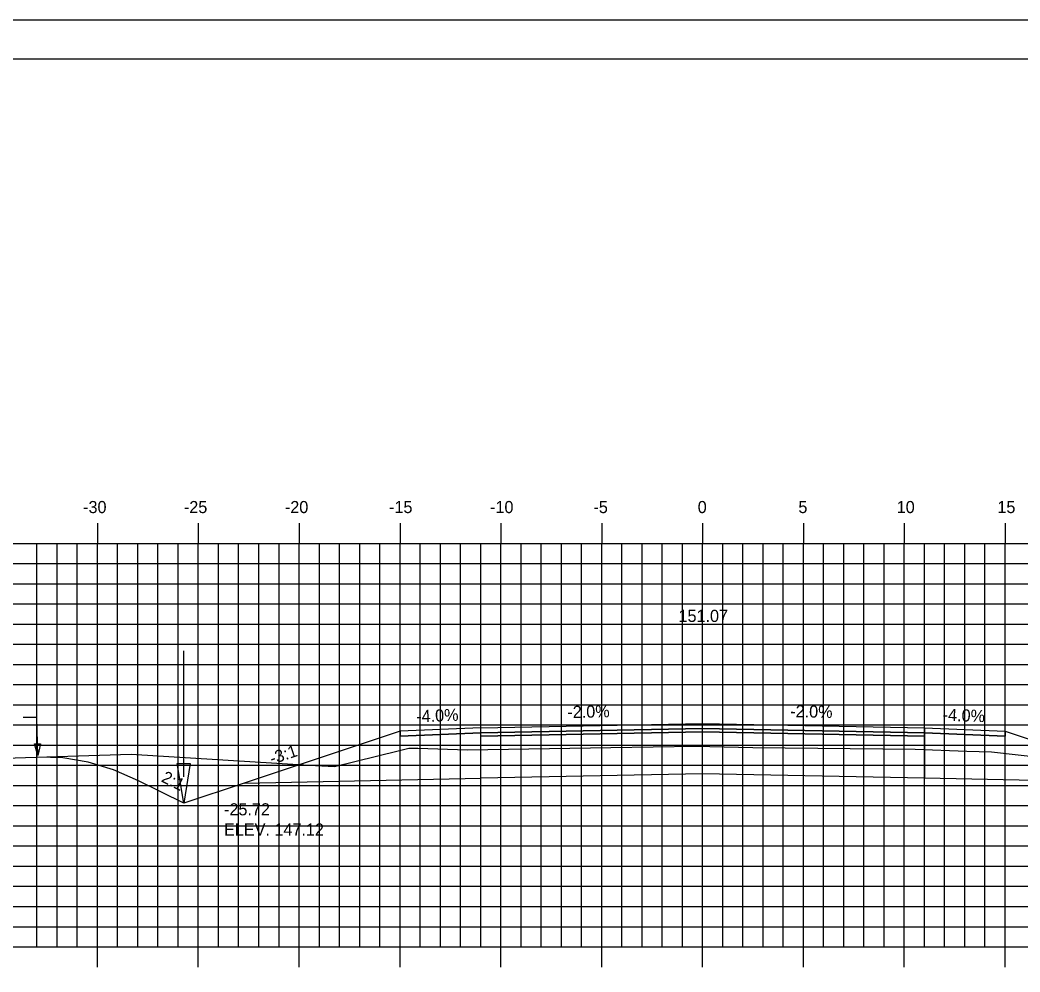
# Model space of a CAD drawing. Extents: x 1147190 to 1147360, y 608981 to 609091.
# Drawn here: x 1147239.1 to 1147288.68, y 609044.09 to 609091.28 of the extents above; entities that cross this region are included whole.
import ezdxf

# ---------------------------------------------------------------- set-up
doc = ezdxf.new("R2010")
doc.units = 0
for name, color, linetype in [('ANNOTATION', 7, 'Continuous'), ('BORDER', 7, 'Continuous'), ('D_Drainage_Ditch_Line', 7, 'Continuous'), ('D_Roadway_Centerline', 7, 'Continuous'), ('D_Roadway_Centerline_Text', 7, 'Continuous'), ('D_Roadway_Edge_Shoulder', 7, 'Continuous'), ('D_Roadway_Edge_TW', 7, 'Continuous'), ('D_Roadway_Pavement', 7, 'Continuous'), ('D_Roadway_SlopeLines', 7, 'Continuous'), ('D_Roadway_SubGrade', 7, 'Continuous'), ('D_Text_Standard', 7, 'Continuous'), ('H_V ANNOTATION', 7, 'Continuous'), ('MAJOR', 7, 'Continuous'), ('MINOR', 7, 'Continuous'), ('PLOT BOUNDARY', 7, 'Continuous'), ('S_Roadway_Centerline', 7, 'Continuous')]:
    doc.layers.add(name, color=color, linetype=linetype)

msp = doc.modelspace()

# ---------------------------------------------------------------- linework, layer by layer
at = {"layer": 'BORDER'}
msp.add_lwpolyline([(1147197.941, 608984.335), (1147357.941, 608984.335), (1147357.941, 609089.335), (1147197.941, 609089.335)], close=True, dxfattribs=at)
at = {"layer": 'D_Drainage_Ditch_Line'}
msp.add_line((1147247.216, 609053.765), (1147247.217, 609060.009), dxfattribs=at)
msp.add_lwpolyline([(1147246.888, 609054.422), (1147247.544, 609054.422), (1147247.216, 609052.453)], close=True, dxfattribs=at)
at = {"layer": 'D_Roadway_Edge_Shoulder'}
for points in [[(1147261.941, 609056.188), (1147257.941, 609056.028), (1147257.941, 609055.778), (1147261.941, 609055.938)], [(1147283.941, 609056.188), (1147287.941, 609056.028), (1147287.941, 609055.778), (1147283.941, 609055.938)]]:
    msp.add_lwpolyline(points, close=True, dxfattribs=at)
at = {"layer": 'D_Roadway_Edge_TW'}
msp.add_lwpolyline([(1147261.941, 609055.938), (1147261.941, 609056.188), (1147272.941, 609056.408), (1147283.941, 609056.188), (1147283.941, 609055.938), (1147272.941, 609056.158)], close=True, dxfattribs=at)
at = {"layer": 'D_Roadway_Pavement'}
msp.add_lwpolyline([(1147261.941, 609055.771), (1147261.941, 609055.938), (1147272.941, 609056.158), (1147283.941, 609055.938), (1147283.941, 609055.771), (1147272.941, 609055.991)], close=True, dxfattribs=at)
at = {"layer": 'D_Roadway_SlopeLines'}
for points in [[(1147247.216, 609052.453), (1147244.981, 609053.571), (1147243.731, 609054.113), (1147242.481, 609054.488), (1147241.231, 609054.698), (1147239.981, 609054.741)], [(1147250.216, 609053.453), (1147247.216, 609052.453)]]:
    msp.add_lwpolyline(points, dxfattribs=at)
at = {"layer": 'D_Roadway_SubGrade'}
for points in [[(1147261.941, 609055.771), (1147261.941, 609055.938), (1147257.941, 609055.778), (1147257.941, 609056.028), (1147257.94, 609056.028), (1147250.216, 609053.453), (1147261.941, 609053.688)], [(1147261.941, 609053.688), (1147261.941, 609055.771), (1147272.941, 609055.991), (1147283.941, 609055.771), (1147283.941, 609053.688), (1147272.941, 609053.908)], [(1147283.941, 609055.771), (1147283.941, 609055.938), (1147287.941, 609055.778), (1147287.941, 609056.028), (1147287.941, 609056.028), (1147295.664, 609053.453), (1147283.941, 609053.688)]]:
    msp.add_lwpolyline(points, close=True, dxfattribs=at)
at = {"layer": 'D_Text_Standard'}
msp.add_lwpolyline([(1147239.981, 609054.821), (1147239.939, 609056.696), (1147239.259, 609056.696)], dxfattribs=at)
msp.add_lwpolyline([(1147239.981, 609054.821), (1147239.823, 609055.399), (1147240.114, 609055.406)], close=True, dxfattribs=at)
at = {"layer": 'MAJOR'}
for p, q in [((1147242.941, 609066.337), (1147242.941, 609065.335)), ((1147247.941, 609066.337), (1147247.941, 609065.335)), ((1147252.941, 609066.337), (1147252.941, 609065.335)), ((1147257.941, 609066.337), (1147257.941, 609065.335)), ((1147262.941, 609066.337), (1147262.941, 609065.335)), ((1147267.941, 609066.337), (1147267.941, 609065.335)), ((1147272.941, 609066.337), (1147272.941, 609065.335)), ((1147277.941, 609066.337), (1147277.941, 609065.335)), ((1147282.941, 609066.337), (1147282.941, 609065.335)), ((1147287.941, 609066.337), (1147287.941, 609065.335)), ((1147202.941, 609065.335), (1147342.941, 609065.335)), ((1147202.941, 609065.335), (1147342.941, 609065.335)), ((1147242.941, 609045.335), (1147242.941, 609065.335)), ((1147247.941, 609045.335), (1147247.941, 609065.335)), ((1147252.941, 609045.335), (1147252.941, 609065.335)), ((1147257.941, 609045.335), (1147257.941, 609065.335)), ((1147262.941, 609045.335), (1147262.941, 609065.335)), ((1147267.941, 609045.335), (1147267.941, 609065.335)), ((1147272.941, 609045.335), (1147272.941, 609065.335)), ((1147277.941, 609045.335), (1147277.941, 609065.335)), ((1147282.941, 609045.335), (1147282.941, 609065.335)), ((1147287.941, 609045.335), (1147287.941, 609065.335)), ((1147202.941, 609060.335), (1147342.941, 609060.335)), ((1147202.941, 609055.335), (1147342.941, 609055.335)), ((1147202.941, 609050.335), (1147342.941, 609050.335)), ((1147202.941, 609045.335), (1147342.941, 609045.335)), ((1147202.941, 609045.335), (1147342.941, 609045.335)), ((1147242.941, 609044.333), (1147242.941, 609045.335)), ((1147247.941, 609044.333), (1147247.941, 609045.335)), ((1147252.941, 609044.333), (1147252.941, 609045.335)), ((1147257.941, 609044.333), (1147257.941, 609045.335)), ((1147262.941, 609044.333), (1147262.941, 609045.335)), ((1147267.941, 609044.333), (1147267.941, 609045.335)), ((1147272.941, 609044.333), (1147272.941, 609045.335)), ((1147277.941, 609044.333), (1147277.941, 609045.335)), ((1147282.941, 609044.333), (1147282.941, 609045.335)), ((1147287.941, 609044.333), (1147287.941, 609045.335))]:
    msp.add_line(p, q, dxfattribs=at)
at = {"layer": 'MINOR'}
for p, q in [((1147239.941, 609045.335), (1147239.941, 609065.335)), ((1147240.941, 609045.335), (1147240.941, 609065.335)), ((1147241.941, 609045.335), (1147241.941, 609065.335)), ((1147243.941, 609045.335), (1147243.941, 609065.335)), ((1147244.941, 609045.335), (1147244.941, 609065.335)), ((1147245.941, 609045.335), (1147245.941, 609065.335)), ((1147246.941, 609045.335), (1147246.941, 609065.335)), ((1147248.941, 609045.335), (1147248.941, 609065.335)), ((1147249.941, 609045.335), (1147249.941, 609065.335)), ((1147250.941, 609045.335), (1147250.941, 609065.335)), ((1147251.941, 609045.335), (1147251.941, 609065.335)), ((1147253.941, 609045.335), (1147253.941, 609065.335)), ((1147254.941, 609045.335), (1147254.941, 609065.335)), ((1147255.941, 609045.335), (1147255.941, 609065.335)), ((1147256.941, 609045.335), (1147256.941, 609065.335)), ((1147258.941, 609045.335), (1147258.941, 609065.335)), ((1147259.941, 609045.335), (1147259.941, 609065.335)), ((1147260.941, 609045.335), (1147260.941, 609065.335)), ((1147261.941, 609045.335), (1147261.941, 609065.335)), ((1147263.941, 609045.335), (1147263.941, 609065.335)), ((1147264.941, 609045.335), (1147264.941, 609065.335)), ((1147265.941, 609045.335), (1147265.941, 609065.335)), ((1147266.941, 609045.335), (1147266.941, 609065.335)), ((1147268.941, 609045.335), (1147268.941, 609065.335)), ((1147269.941, 609045.335), (1147269.941, 609065.335)), ((1147270.941, 609045.335), (1147270.941, 609065.335)), ((1147271.941, 609045.335), (1147271.941, 609065.335)), ((1147273.941, 609045.335), (1147273.941, 609065.335)), ((1147274.941, 609045.335), (1147274.941, 609065.335)), ((1147275.941, 609045.335), (1147275.941, 609065.335)), ((1147276.941, 609045.335), (1147276.941, 609065.335)), ((1147278.941, 609045.335), (1147278.941, 609065.335)), ((1147279.941, 609045.335), (1147279.941, 609065.335)), ((1147280.941, 609045.335), (1147280.941, 609065.335)), ((1147281.941, 609045.335), (1147281.941, 609065.335)), ((1147283.941, 609045.335), (1147283.941, 609065.335)), ((1147284.941, 609045.335), (1147284.941, 609065.335)), ((1147285.941, 609045.335), (1147285.941, 609065.335)), ((1147286.941, 609045.335), (1147286.941, 609065.335)), ((1147202.941, 609064.335), (1147342.941, 609064.335)), ((1147202.941, 609063.335), (1147342.941, 609063.335)), ((1147202.941, 609062.335), (1147342.941, 609062.335)), ((1147202.941, 609061.335), (1147342.941, 609061.335)), ((1147202.941, 609059.335), (1147342.941, 609059.335)), ((1147202.941, 609058.335), (1147342.941, 609058.335)), ((1147202.941, 609057.335), (1147342.941, 609057.335)), ((1147202.941, 609056.335), (1147342.941, 609056.335)), ((1147202.941, 609054.335), (1147342.941, 609054.335)), ((1147202.941, 609053.335), (1147342.941, 609053.335)), ((1147202.941, 609052.335), (1147342.941, 609052.335)), ((1147202.941, 609051.335), (1147342.941, 609051.335)), ((1147202.941, 609049.335), (1147342.941, 609049.335)), ((1147202.941, 609048.335), (1147342.941, 609048.335)), ((1147202.941, 609047.335), (1147342.941, 609047.335)), ((1147202.941, 609046.335), (1147342.941, 609046.335))]:
    msp.add_line(p, q, dxfattribs=at)
at = {"layer": 'PLOT BOUNDARY'}
msp.add_lwpolyline([(1147189.848, 608981.276), (1147359.848, 608981.276), (1147359.848, 609091.276), (1147189.848, 609091.276)], close=True, dxfattribs=at)
at = {"layer": 'S_Roadway_Centerline'}
msp.add_lwpolyline([(1147218.688, 609053.977), (1147226.482, 609054.305), (1147226.795, 609054.318), (1147244.605, 609054.889), (1147253.434, 609054.334), (1147254.688, 609054.274), (1147257.845, 609055.05), (1147258.383, 609055.178), (1147258.823, 609055.179), (1147261.29, 609055.101), (1147268.386, 609055.21), (1147272.587, 609055.279), (1147275.438, 609055.212), (1147283.483, 609055.129), (1147286.037, 609055.041), (1147287.273, 609054.996), (1147292.854, 609054.376), (1147294.865, 609054.203), (1147300.019, 609054.043), (1147301.689, 609053.963), (1147303.16, 609054.01), (1147308.976, 609054.019), (1147310.153, 609054.07), (1147311.998, 609054.066)], dxfattribs=at)

# ---------------------------------------------------------------- texts
at = {"layer": 'ANNOTATION'}
for s, rotation, p in [('-4.0%', 2.2906, (1147258.757, 609056.461)), ('-2.0%', 1.1458, (1147266.244, 609056.674)), ('-2.0%', 358.8542, (1147277.284, 609056.721)), ('-4.0%', 357.7094, (1147284.837, 609056.553)), ('-3:1', 18.4348, (1147251.595, 609054.367)), ('2:1', 333.4349, (1147246.066, 609053.546))]:
    msp.add_text(s, height=0.6, rotation=rotation, dxfattribs=at).set_placement(p)
at = {"layer": 'D_Roadway_Centerline'}
for s, p in [('C', (1147272.936, 609056.408)), ('L', (1147272.941, 609056.4))]:
    msp.add_text(s, height=0.0146, dxfattribs=at).set_placement(p)
at = {"layer": 'D_Roadway_Centerline_Text'}
msp.add_text('151.07', height=0.6, dxfattribs=at).set_placement((1147271.748, 609061.44))
at = {"layer": 'D_Text_Standard'}
for s, p in [('-25.72', (1147249.216, 609051.853)), ('ELEV. 147.12', (1147249.216, 609050.851))]:
    msp.add_text(s, height=0.6, dxfattribs=at).set_placement(p)
at = {"layer": 'H_V ANNOTATION'}
for s, p in [('-30', (1147242.229, 609066.835)), ('-25', (1147247.226, 609066.835)), ('-20', (1147252.234, 609066.835)), ('-15', (1147257.398, 609066.835)), ('-10', (1147262.406, 609066.835)), ('-5', (1147267.531, 609066.835)), ('0', (1147272.7, 609066.835)), ('5', (1147277.692, 609066.835)), ('10', (1147282.566, 609066.835)), ('15', (1147287.558, 609066.835))]:
    msp.add_text(s, height=0.6, dxfattribs=at).set_placement(p)
at = {"layer": 'S_Roadway_Centerline'}
for s, p in [('L', (1147272.579, 609055.272)), ('C', (1147272.582, 609055.279))]:
    msp.add_text(s, height=0.0146, dxfattribs=at).set_placement(p)

doc.saveas('drawing.dxf')
